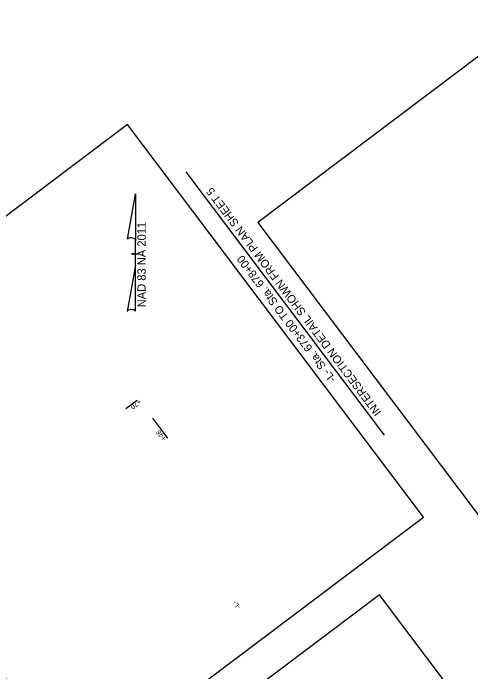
# Model space of a CAD drawing. Extents: x 1262861 to 1264804, y 775326 to 777329.
# Drawn here: x 1263399 to 1263867, y 776290 to 776963 of the extents above; entities that cross this region are included whole.
import ezdxf

# ---------------------------------------------------------------- set-up
doc = ezdxf.new("R2010")
doc.units = 0
for name, color, linetype in [('Old_Level_1', 7, 'Continuous'), ('Prop Dimension', 7, 'Continuous'), ('Prop Dimension Text', 7, 'Continuous'), ('Prop Horizontal Alignment Curve and Spiral Data', 7, 'Continuous'), ('Sheet Typical CELL', 7, 'Continuous')]:
    doc.layers.add(name, color=color, linetype=linetype)

msp = doc.modelspace()

# ---------------------------------------------------------------- linework, layer by layer
at = {"layer": 'Old_Level_1'}
for p, q in [((1263515.99, 776731.87), (1263524.21, 776778.22)), ((1263524.26, 776778.22), (1263524.21, 776778.22)), ((1263524.26, 776778.22), (1263524.21, 776778.22)), ((1263524.26, 776778.22), (1263524.24, 776730.42)), ((1263524.23, 776705.62), (1263524.24, 776731.82)), ((1263524.24, 776730.42), (1263524.24, 776731.77)), ((1263520.23, 776717.22), (1263520.18, 776717.22)), ((1263523.78, 776717.22), (1263520.23, 776717.22)), ((1263520.28, 776717.22), (1263528.28, 776717.21)), ((1263524.23, 776705.62), (1263515.86, 776658.37)), ((1263524.26, 776658.57), (1263524.23, 776705.62))]:
    msp.add_line(p, q, dxfattribs=at)
for centre, start_param, end_param in [((1263520.12, 776731.37), 0.216388, 2.908219), ((1263520.09, 776658.2), 0.201328, 3.141593)]:
    msp.add_ellipse(centre, major_axis=(4.23, -0.03), ratio=0.461098, start_param=start_param, end_param=end_param, dxfattribs=at)
at = {"layer": 'Prop Dimension'}
for p, q in [((1263514.6, 776559.18), (1263526.11, 776567.85)), ((1263557.19, 776528.99), (1263541.85, 776549.36))]:
    msp.add_line(p, q, dxfattribs=at)
at = {"layer": 'Prop Horizontal Alignment Curve and Spiral Data'}
msp.add_line((1263778.41, 776532.09), (1263576.09, 776800.7), dxfattribs=at)
at = {"layer": 'Sheet Typical CELL'}
for points in [[(1264392.94, 776351.84), (1263932.86, 776962.66), (1263649.33, 776749.11), (1264109.41, 776138.28)], [(1263818.15, 776448.22), (1263516.3, 776848.97), (1263165.03, 776584.39), (1263466.88, 776183.64)], [(1263511.39, 776171.64), (1263961, 775574.71), (1264222.92, 775771.99), (1263773.3, 776368.92)]]:
    msp.add_lwpolyline(points, close=True, dxfattribs=at)

# ---------------------------------------------------------------- texts
at = {"layer": 'Old_Level_1'}
msp.add_text('NAD 83 NA 2011', height=8.5, rotation=89.97606, dxfattribs=at).set_placement((1263534.73, 776662.47))
at = {"layer": 'Prop Dimension'}
msp.add_text('-L-', height=5, rotation=126.98742, dxfattribs=at).set_placement((1263631.8, 776356.7))
at = {"layer": 'Prop Dimension Text'}
for s, rotation, p in [(' +70', 218.01434, (1263529.34, 776570.15)), ('+46', 126.98742, (1263555.89, 776528.53))]:
    msp.add_text(s, height=5, rotation=rotation, dxfattribs=at).set_placement(p)
at = {"layer": 'Prop Horizontal Alignment Curve and Spiral Data'}
for s, p in [('INTERSECTION DETAIL SHOWN FROM PLAN SHEET 5 ', (1263775.76, 776555.52)), ('-L- Sta. 673+00 TO Sta. 678+00', (1263729.34, 776589.41))]:
    msp.add_text(s, height=8.3203, rotation=126.98742, dxfattribs=at).set_placement(p)

doc.saveas('drawing.dxf')
